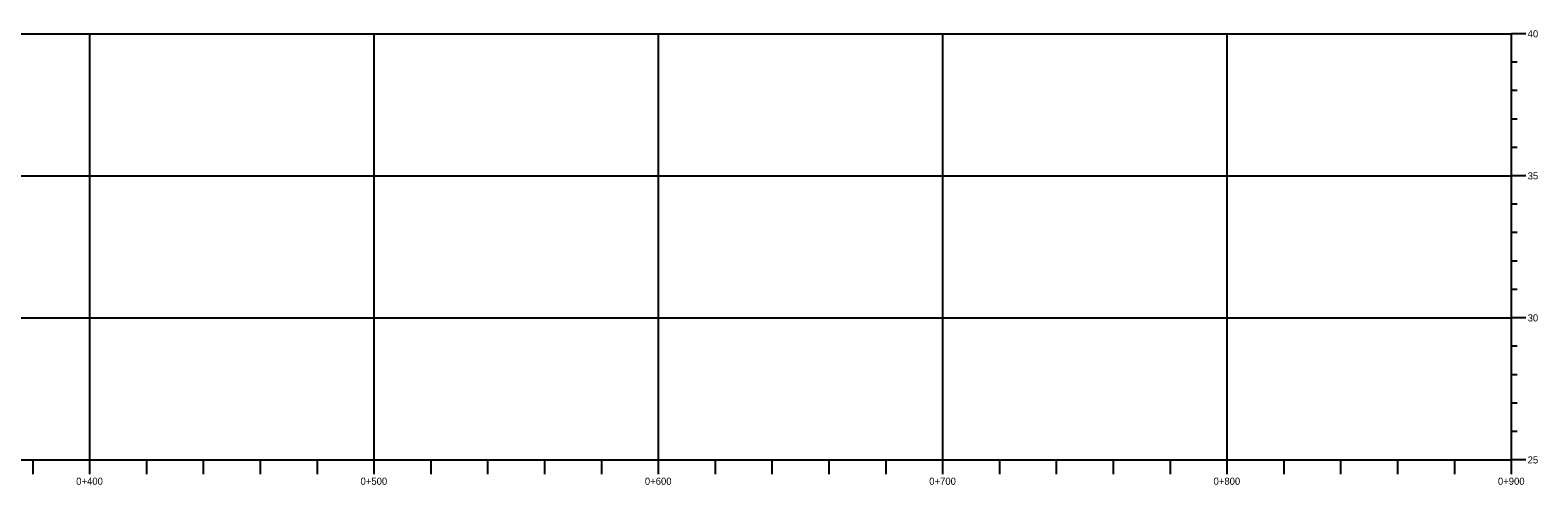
# Model space of a CAD drawing. Extents: x 0 to 513042, y 0 to 6212511.
# Drawn here: x 512512 to 513042, y 6211831 to 6211991 of the extents above; entities that cross this region are included whole.
import ezdxf

# ---------------------------------------------------------------- set-up
doc = ezdxf.new("R2010")
doc.units = 0
for name, color, linetype in [('TV_G_CL---', 7, 'Continuous'), ('TV_G_DTM_Exter', 7, 'Continuous'), ('TV_L_VER_Punkt', 7, 'Continuous')]:
    doc.layers.add(name, color=color, linetype=linetype)

msp = doc.modelspace()

# ---------------------------------------------------------------- linework, layer by layer
at = {"layer": 'TV_G_CL---'}
for p, q in [((513033.07, 6211840.01), (513033.07, 6211990.01)), ((511933.07, 6211840.01), (513033.07, 6211840.01))]:
    msp.add_line(p, q, dxfattribs=at)
at = {"layer": 'TV_G_DTM_Exter'}
for p, q in [((513038.07, 6211990.01), (513033.07, 6211990.01)), ((513038.07, 6211990.01), (513033.07, 6211990.01)), ((513035.07, 6211980.01), (513033.07, 6211980.01)), ((513035.07, 6211970.01), (513033.07, 6211970.01)), ((513035.07, 6211960.01), (513033.07, 6211960.01)), ((513035.07, 6211950.01), (513033.07, 6211950.01)), ((513038.07, 6211940.01), (513033.07, 6211940.01)), ((513035.07, 6211930.01), (513033.07, 6211930.01)), ((513035.07, 6211920.01), (513033.07, 6211920.01)), ((513035.07, 6211910.01), (513033.07, 6211910.01)), ((513035.07, 6211900.01), (513033.07, 6211900.01)), ((513038.07, 6211890.01), (513033.07, 6211890.01)), ((513035.07, 6211880.01), (513033.07, 6211880.01)), ((513035.07, 6211870.01), (513033.07, 6211870.01)), ((513035.07, 6211860.01), (513033.07, 6211860.01)), ((513035.07, 6211850.01), (513033.07, 6211850.01)), ((512513.07, 6211835.01), (512513.07, 6211840.01)), ((512533.07, 6211835.01), (512533.07, 6211840.01)), ((512553.07, 6211835.01), (512553.07, 6211840.01)), ((512573.07, 6211835.01), (512573.07, 6211840.01)), ((512593.07, 6211835.01), (512593.07, 6211840.01)), ((512613.07, 6211835.01), (512613.07, 6211840.01)), ((512633.07, 6211835.01), (512633.07, 6211840.01)), ((512653.07, 6211835.01), (512653.07, 6211840.01)), ((512673.07, 6211835.01), (512673.07, 6211840.01)), ((512693.07, 6211835.01), (512693.07, 6211840.01)), ((512713.07, 6211835.01), (512713.07, 6211840.01)), ((512733.07, 6211835.01), (512733.07, 6211840.01)), ((512753.07, 6211835.01), (512753.07, 6211840.01)), ((512773.07, 6211835.01), (512773.07, 6211840.01)), ((512793.07, 6211835.01), (512793.07, 6211840.01)), ((512813.07, 6211835.01), (512813.07, 6211840.01)), ((512833.07, 6211835.01), (512833.07, 6211840.01)), ((512853.07, 6211835.01), (512853.07, 6211840.01)), ((512873.07, 6211835.01), (512873.07, 6211840.01)), ((512893.07, 6211835.01), (512893.07, 6211840.01)), ((512913.07, 6211835.01), (512913.07, 6211840.01)), ((512933.07, 6211835.01), (512933.07, 6211840.01)), ((512953.07, 6211835.01), (512953.07, 6211840.01)), ((512973.07, 6211835.01), (512973.07, 6211840.01)), ((512993.07, 6211835.01), (512993.07, 6211840.01)), ((513013.07, 6211835.01), (513013.07, 6211840.01)), ((513038.07, 6211840.01), (513033.07, 6211840.01)), ((513033.07, 6211835.01), (513033.07, 6211840.01))]:
    msp.add_line(p, q, dxfattribs=at)
at = {"layer": 'TV_L_VER_Punkt'}
for p, q in [((511933.07, 6211990.01), (513033.07, 6211990.01)), ((511933.07, 6211990.01), (513033.07, 6211990.01)), ((512533.07, 6211840.01), (512533.07, 6211990.01)), ((512633.07, 6211840.01), (512633.07, 6211990.01)), ((512733.07, 6211840.01), (512733.07, 6211990.01)), ((512833.07, 6211840.01), (512833.07, 6211990.01)), ((512933.07, 6211840.01), (512933.07, 6211990.01)), ((511933.07, 6211940.01), (513033.07, 6211940.01)), ((511933.07, 6211890.01), (513033.07, 6211890.01))]:
    msp.add_line(p, q, dxfattribs=at)

# ---------------------------------------------------------------- texts
for s, p in [('40', (513038.71, 6211988.76)), ('40', (513038.71, 6211988.76)), ('35', (513038.7, 6211938.76)), ('30', (513038.71, 6211888.76)), ('25', (513038.7, 6211838.76)), ('0+400', (512528.25, 6211831.26)), ('0+500', (512628.25, 6211831.26)), ('0+600', (512728.25, 6211831.26)), ('0+700', (512828.25, 6211831.26)), ('0+800', (512928.25, 6211831.26)), ('0+900', (513028.25, 6211831.26))]:
    msp.add_text(s, height=2.5).set_placement(p)

doc.saveas('drawing.dxf')
